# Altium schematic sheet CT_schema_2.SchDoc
size 287 x 169 mm
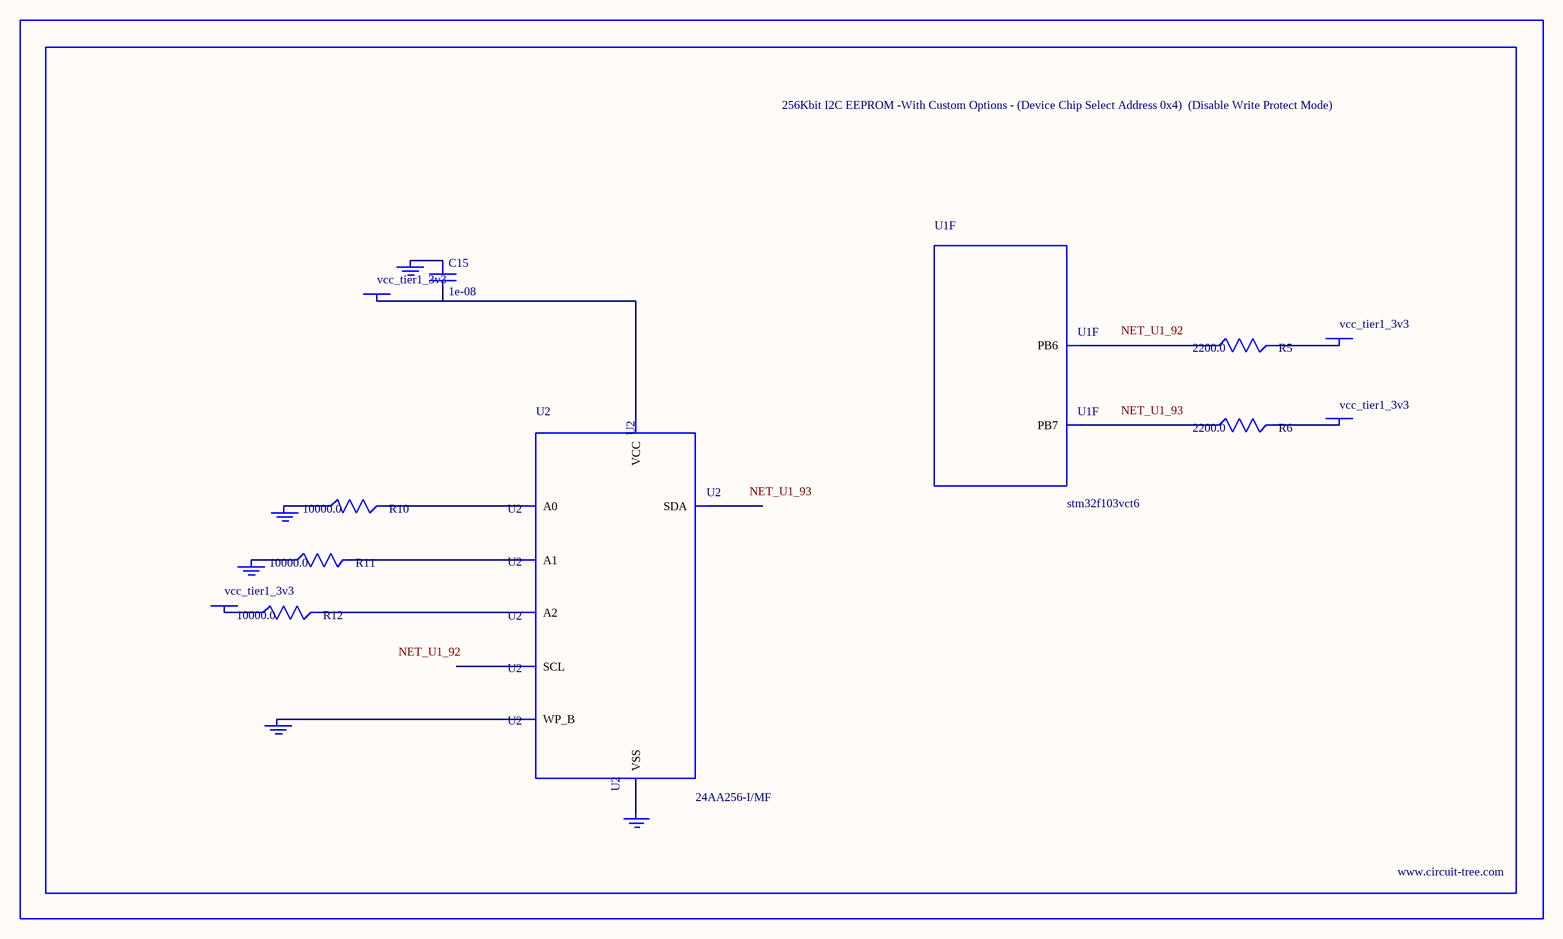
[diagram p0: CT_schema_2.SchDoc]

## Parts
BORDER1  (no value)
C15  1e-08  [C0402]
GND_INSTANCE_1_0  (no value)
GND_INSTANCE_1_1  (no value)
GND_INSTANCE_1_2  (no value)
GND_INSTANCE_1_3  (no value)
GND_INSTANCE_1_4  (no value)
POWER_INSTANCE_1_0  vcc_tier1_3v3
POWER_INSTANCE_1_1  vcc_tier1_3v3
POWER_INSTANCE_1_2  vcc_tier1_3v3
POWER_INSTANCE_1_3  vcc_tier1_3v3
R5  2200.0  [R0603]
R6  2200.0  [R0603]
R10  10000.0  [R0603]
R11  10000.0  [R0603]
R12  10000.0  [R0603]
U1  stm32f103vct6  [LQFP100]  (part F of 10)
U2  24AA256-I/MF  [DFN8-S]

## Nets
NetC15_1: C15.1 GND_INSTANCE_1_3.0(GND)
NetC15_2: C15.2 POWER_INSTANCE_1_1.0(PWR) U2.8(VCC)
NetGND_INSTANCE_1_0_0: GND_INSTANCE_1_0.0(GND) R10.1
NetGND_INSTANCE_1_1_0: GND_INSTANCE_1_1.0(GND) R11.1
NetGND_INSTANCE_1_2_0: GND_INSTANCE_1_2.0(GND) U2.7(WP_B)
NetGND_INSTANCE_1_4_0: GND_INSTANCE_1_4.0(GND) U2.4(VSS)
NetPOWER_INSTANCE_1_0_0: POWER_INSTANCE_1_0.0(PWR) R12.1
NetPOWER_INSTANCE_1_2_0: POWER_INSTANCE_1_2.0(PWR) R5.2
NetPOWER_INSTANCE_1_3_0: POWER_INSTANCE_1_3.0(PWR) R6.2
NetR5_1: R5.1 U1.92(PB6)
NetR6_1: R6.1 U1.93(PB7)
NetR10_2: R10.2 U2.1(A0)
NetR11_2: R11.2 U2.2(A1)
NetR12_2: R12.2 U2.3(A2)

Not connected (* = marked no-connect by the designer): U2 5(SDA) 6(SCL)

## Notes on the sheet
- Labels drawn without touching a wire or pin: NET_U1_92, NET_U1_93

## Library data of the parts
BORDER1 = BORDER_PAGE1
C15 = C0402C103K3RAC
GND_INSTANCE_1_0-GND_INSTANCE_1_4 = GND
POWER_INSTANCE_1_0-POWER_INSTANCE_1_3 = PWR
R5 R6 = RC0603JR-072K2L
R10-R12 = RC0603JR-0710KL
